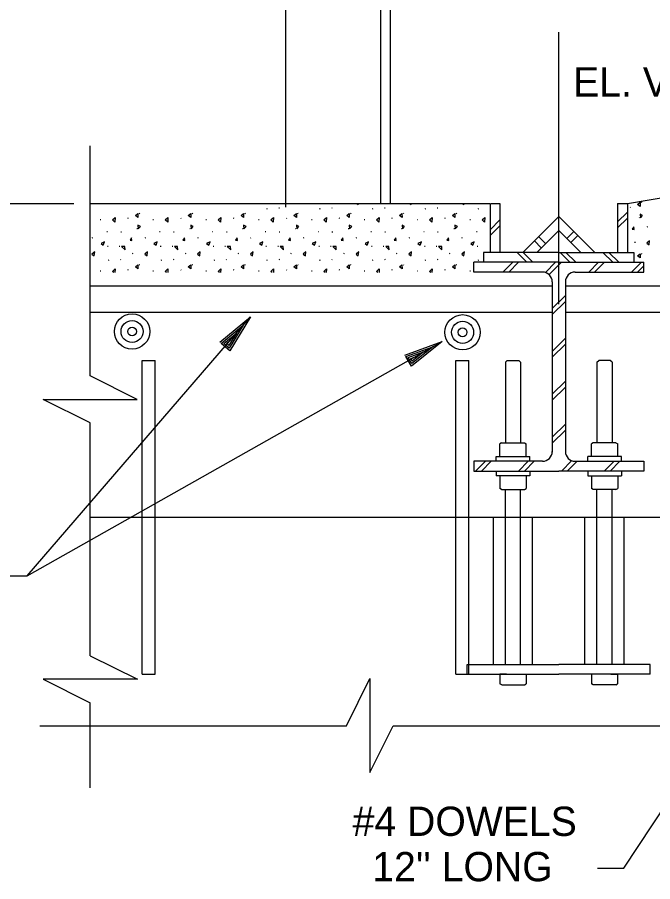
# Model space of a CAD drawing. Extents: x 0 to 320, y -4 to 473.
# Drawn here: x 7.218 to 10.256, y 2.461 to 6.592 of the extents above; entities that cross this region are included whole.
import ezdxf

# ---------------------------------------------------------------- set-up
doc = ezdxf.new("R2010")
doc.units = 0
for name, color, linetype in [('Level 2', 7, 'Continuous'), ('Level 22', 7, 'Continuous'), ('Level 3', 7, 'Continuous'), ('Level 44', 7, 'Continuous'), ('Level 50', 7, 'Continuous')]:
    doc.layers.add(name, color=color, linetype=linetype)

msp = doc.modelspace()

# ---------------------------------------------------------------- linework, layer by layer
at = {"layer": 'Level 2'}
for p, q in [((8.5026, 5.6844), (8.5026, 8.1261)), ((8.9557, 5.7009), (8.9557, 8.1261)), ((9.0026, 5.7025), (9.0026, 8.1261)), ((10.1354, 5.7025), (10.8854, 5.8276)), ((7.5674, 5.7025), (9.4791, 5.7025)), ((9.4791, 5.7025), (9.4791, 5.4682)), ((9.4836, 5.7025), (9.526, 5.7025)), ((9.526, 5.7025), (9.526, 5.4682)), ((10.0885, 5.7025), (10.0885, 5.4682)), ((10.0885, 5.7025), (10.1354, 5.7025)), ((10.1354, 5.7025), (10.1354, 5.4682)), ((10.0885, 5.6139), (10.1354, 5.6608)), ((9.4791, 5.577), (9.526, 5.6238)), ((9.8072, 5.64), (9.6354, 5.4682)), ((9.8072, 5.64), (9.9791, 5.4682)), ((10.0885, 5.5856), (10.1354, 5.6325)), ((9.4791, 5.5487), (9.526, 5.5956)), ((9.8072, 5.5738), (9.7017, 5.4682)), ((9.7439, 5.5104), (9.7108, 5.5436)), ((9.8072, 5.5738), (9.9128, 5.4682)), ((9.8461, 5.5348), (9.8793, 5.568)), ((9.8651, 5.5159), (9.8983, 5.549)), ((9.7237, 5.4902), (9.6905, 5.5233)), ((9.8072, 5.4682), (9.4479, 5.4682)), ((9.4479, 5.4682), (9.4479, 5.4213)), ((9.6551, 5.4213), (9.6082, 5.4682)), ((9.6833, 5.4213), (9.6365, 5.4682)), ((9.8072, 5.4682), (10.1666, 5.4682)), ((9.8601, 5.4213), (9.8132, 5.4682)), ((9.8884, 5.4213), (9.8415, 5.4682)), ((10.0652, 5.4213), (10.0183, 5.4682)), ((10.0935, 5.4213), (10.0466, 5.4682)), ((10.1666, 5.4682), (10.1666, 5.4213)), ((9.8072, 5.4213), (9.401, 5.4213)), ((9.401, 5.3744), (9.401, 5.4213)), ((9.54, 5.3744), (9.5869, 5.4213)), ((9.5683, 5.3744), (9.6151, 5.4213)), ((9.7429, 5.3723), (9.7919, 5.4213)), ((9.7609, 5.362), (9.8202, 5.4213)), ((9.8072, 5.4213), (10.2135, 5.4213)), ((9.9501, 5.3744), (9.997, 5.4213)), ((9.9784, 5.3744), (10.0253, 5.4213)), ((10.1552, 5.3744), (10.202, 5.4213)), ((10.2135, 5.3744), (10.2135, 5.4213)), ((9.7291, 5.3744), (9.401, 5.3744)), ((9.8854, 5.3744), (10.2135, 5.3744)), ((10.1834, 5.3744), (10.2135, 5.4045)), ((9.776, 5.3068), (7.5674, 5.3068)), ((9.776, 5.3275), (9.776, 4.5135)), ((9.8385, 5.3275), (9.8385, 4.5135)), ((11.4166, 5.3068), (9.8385, 5.3068)), ((9.776, 5.2003), (9.8385, 5.2628)), ((9.776, 5.172), (9.8385, 5.2345)), ((9.776, 5.1818), (7.5674, 5.1818)), ((11.4166, 5.1818), (9.8385, 5.1818)), ((9.776, 4.9953), (9.8385, 5.0578)), ((9.776, 4.967), (9.8385, 5.0295)), ((7.8151, 3.4525), (7.8151, 4.9525)), ((7.8776, 3.4525), (7.8776, 4.9525)), ((9.3151, 3.4525), (9.3151, 4.9525)), ((9.3776, 3.4525), (9.3776, 4.9525)), ((9.5519, 4.9434), (9.561, 4.9525)), ((9.5521, 4.9434), (9.5521, 4.5583)), ((9.561, 4.9525), (9.6156, 4.9525)), ((9.6247, 4.9434), (9.6156, 4.9525)), ((9.6249, 4.9434), (9.6249, 4.5583)), ((9.9896, 4.9434), (9.9896, 4.5583)), ((9.9898, 4.9434), (9.9989, 4.9525)), ((10.0535, 4.9525), (9.9989, 4.9525)), ((10.0626, 4.9434), (10.0535, 4.9525)), ((10.0624, 4.9434), (10.0624, 4.5583)), ((9.776, 4.7902), (9.8385, 4.8527)), ((9.776, 4.7619), (9.8385, 4.8244)), ((9.776, 4.5851), (9.8385, 4.6476)), ((9.776, 4.5568), (9.8385, 4.6193)), ((9.5341, 4.5583), (9.5257, 4.5534)), ((9.5257, 4.4938), (9.5257, 4.5534)), ((9.5341, 4.5583), (9.6429, 4.5583)), ((9.6429, 4.5583), (9.6513, 4.5534)), ((9.6513, 4.4938), (9.6513, 4.5534)), ((9.9716, 4.5583), (9.9632, 4.5534)), ((9.9632, 4.4938), (9.9632, 4.5534)), ((10.0804, 4.5583), (9.9716, 4.5583)), ((10.0804, 4.5583), (10.0888, 4.5534)), ((10.0888, 4.4938), (10.0888, 4.5534)), ((9.7291, 4.4703), (9.401, 4.4703)), ((9.401, 4.4703), (9.401, 4.4235)), ((9.4093, 4.4235), (9.4561, 4.4703)), ((9.4376, 4.4235), (9.4844, 4.4703)), ((9.5082, 4.4938), (9.6688, 4.4938)), ((9.5082, 4.4703), (9.5082, 4.4938)), ((9.5521, 4.4915), (9.5521, 4.4938)), ((9.6143, 4.4235), (9.6612, 4.4703)), ((9.6249, 4.4915), (9.6249, 4.4938)), ((9.6426, 4.4235), (9.6895, 4.4703)), ((9.6688, 4.4703), (9.6688, 4.4938)), ((9.8194, 4.4235), (9.8692, 4.4732)), ((9.8477, 4.4235), (9.8946, 4.4703)), ((9.8854, 4.4703), (10.2135, 4.4703)), ((10.1063, 4.4938), (9.9457, 4.4938)), ((9.9457, 4.4703), (9.9457, 4.4938)), ((9.9896, 4.4915), (9.9896, 4.4938)), ((10.0245, 4.4235), (10.0713, 4.4703)), ((10.0527, 4.4235), (10.0996, 4.4703)), ((10.0624, 4.4915), (10.0624, 4.4938)), ((10.1063, 4.4703), (10.1063, 4.4938)), ((10.2135, 4.4703), (10.2135, 4.4235)), ((9.401, 4.4235), (9.8072, 4.4235)), ((9.5082, 4.4235), (9.5082, 4.4)), ((9.6688, 4.4235), (9.6688, 4.4)), ((10.2135, 4.4235), (9.8072, 4.4235)), ((9.9457, 4.4235), (9.9457, 4.4)), ((10.1063, 4.4235), (10.1063, 4.4)), ((9.6688, 4.4), (9.5082, 4.4)), ((9.5257, 4.4), (9.5257, 4.3404)), ((9.5521, 4.4023), (9.5521, 4.4)), ((9.6249, 4.4023), (9.6249, 4.4)), ((9.6513, 4.4), (9.6513, 4.3404)), ((9.9457, 4.4), (10.1063, 4.4)), ((9.9632, 4.4), (9.9632, 4.3404)), ((9.9896, 4.4023), (9.9896, 4.4)), ((10.0624, 4.4023), (10.0624, 4.4)), ((10.0888, 4.4), (10.0888, 4.3404)), ((9.5341, 4.3355), (9.5257, 4.3404)), ((9.6429, 4.3355), (9.6513, 4.3404)), ((9.9716, 4.3355), (9.9632, 4.3404)), ((10.0804, 4.3355), (10.0888, 4.3404)), ((9.5341, 4.3355), (9.6429, 4.3355)), ((9.5521, 3.4994), (9.5521, 4.3355)), ((9.6249, 3.4994), (9.6249, 4.3355)), ((10.0804, 4.3355), (9.9716, 4.3355)), ((9.9896, 3.4994), (9.9896, 4.3355)), ((10.0624, 3.4994), (10.0624, 4.3355)), ((7.5674, 4.2025), (14.9124, 4.2025)), ((9.4947, 3.4994), (9.4947, 4.2025)), ((9.6822, 3.4994), (9.6822, 4.2025)), ((9.9322, 3.4994), (9.9322, 4.2025)), ((10.1197, 3.4994), (10.1197, 4.2025)), ((9.3697, 3.4994), (9.8072, 3.4994)), ((9.3697, 3.4525), (9.3697, 3.4994)), ((10.2447, 3.4994), (9.8072, 3.4994)), ((10.2447, 3.4525), (10.2447, 3.4994)), ((9.3697, 3.4525), (9.8072, 3.4525)), ((9.5578, 3.4523), (9.526, 3.4523)), ((9.526, 3.4523), (9.526, 3.4063)), ((9.5525, 3.4546), (9.5525, 3.4523)), ((9.6252, 3.4546), (9.6252, 3.4523)), ((9.6517, 3.4523), (9.6517, 3.4063)), ((10.2447, 3.4525), (9.8072, 3.4525)), ((9.9628, 3.4523), (9.9628, 3.4063)), ((9.9893, 3.4546), (9.9893, 3.4523)), ((10.0567, 3.4523), (10.0884, 3.4523)), ((10.062, 3.4546), (10.062, 3.4523)), ((10.0884, 3.4523), (10.0884, 3.4063)), ((9.5345, 3.4014), (9.526, 3.4063)), ((9.5345, 3.4014), (9.6432, 3.4014)), ((9.6432, 3.4014), (9.6517, 3.4063)), ((9.9713, 3.4014), (9.9628, 3.4063)), ((10.08, 3.4014), (9.9713, 3.4014)), ((10.08, 3.4014), (10.0884, 3.4063))]:
    msp.add_line(p, q, dxfattribs=at)
for centre, start, end in [((9.7291, 5.3275), 0, 90), ((9.8854, 5.3275), 90, 180), ((9.7291, 4.5172), 270, 360), ((9.8854, 4.5172), 180, 270)]:
    msp.add_arc(centre, 0.0469, start, end, dxfattribs=at)
at = {"layer": 'Level 3'}
for p, q in [((8.3326, 5.1604), (8.3326, 5.1604)), ((8.2986, 5.1211), (8.2986, 5.1211))]:
    msp.add_line(p, q, dxfattribs=at)
for points in [[(6.9886, 3.9226), (7.2659, 3.9226), (8.3326, 5.1604)], [(8.187, 5.039), (8.3326, 5.1604), (8.234, 4.9985), (8.1938, 5.0331), (8.2986, 5.1211), (8.2316, 5.0111), (8.2059, 5.0333), (8.266, 5.0832), (8.2293, 5.0237), (8.2187, 5.0329), (8.232, 5.0438)], [(9.9929, 2.5257), (10.1174, 2.5257), (10.8098, 3.5702)]]:
    msp.add_lwpolyline(points, dxfattribs=at)
at = {"layer": 'Level 44'}
for p, q in [((7.5674, 4.8785), (7.5674, 5.9777)), ((6.4616, 5.7025), (7.4884, 5.7025)), ((10.205, 5.7061), (10.2022, 5.7078)), ((8.4132, 5.6765), (8.4098, 5.6756)), ((8.4714, 5.6799), (8.469, 5.679)), ((8.6657, 5.6765), (8.6623, 5.6756)), ((8.7239, 5.6799), (8.7215, 5.679)), ((8.9182, 5.6765), (8.9148, 5.6756)), ((8.9764, 5.6799), (8.974, 5.679)), ((9.1707, 5.6765), (9.1673, 5.6756)), ((9.2289, 5.6799), (9.2265, 5.679)), ((9.4232, 5.6765), (9.4198, 5.6756)), ((10.1505, 5.6829), (10.1478, 5.6841)), ((7.6174, 5.6242), (7.6147, 5.6239)), ((7.75, 5.6302), (7.7473, 5.6314)), ((7.8044, 5.6534), (7.8016, 5.6551)), ((7.8699, 5.6242), (7.8672, 5.6239)), ((8.0025, 5.6302), (7.9998, 5.6314)), ((8.0569, 5.6534), (8.0541, 5.6551)), ((8.1224, 5.6242), (8.1197, 5.6239)), ((8.255, 5.6302), (8.2523, 5.6314)), ((8.3094, 5.6534), (8.3066, 5.6551)), ((8.3749, 5.6242), (8.3722, 5.6239)), ((8.5075, 5.6302), (8.5048, 5.6314)), ((8.5619, 5.6534), (8.5591, 5.6551)), ((8.6274, 5.6242), (8.6247, 5.6239)), ((8.76, 5.6302), (8.7573, 5.6314)), ((8.8144, 5.6534), (8.8116, 5.6551)), ((8.8799, 5.6242), (8.8772, 5.6239)), ((9.0125, 5.6302), (9.0098, 5.6314)), ((9.0669, 5.6534), (9.0641, 5.6551)), ((9.1324, 5.6242), (9.1297, 5.6239)), ((9.265, 5.6302), (9.2623, 5.6314)), ((9.3194, 5.6534), (9.3166, 5.6551)), ((9.3849, 5.6242), (9.3822, 5.6239)), ((10.1937, 5.6343), (10.1912, 5.6345)), ((7.7932, 5.5816), (7.7907, 5.5818)), ((8.0457, 5.5816), (8.0432, 5.5818)), ((8.2982, 5.5816), (8.2957, 5.5818)), ((8.5507, 5.5816), (8.5482, 5.5818)), ((8.8032, 5.5816), (8.8007, 5.5818)), ((9.0557, 5.5816), (9.0532, 5.5818)), ((9.3082, 5.5816), (9.3057, 5.5818)), ((10.2313, 5.5903), (10.2283, 5.5888)), ((7.5782, 5.5375), (7.5752, 5.536)), ((7.649, 5.567), (7.6465, 5.5674)), ((7.7162, 5.5649), (7.7129, 5.5649)), ((7.8307, 5.5375), (7.8277, 5.536)), ((7.9015, 5.567), (7.899, 5.5674)), ((7.9687, 5.5649), (7.9654, 5.5649)), ((8.0832, 5.5375), (8.0802, 5.536)), ((8.154, 5.567), (8.1515, 5.5674)), ((8.2212, 5.5649), (8.2179, 5.5649)), ((8.3357, 5.5375), (8.3327, 5.536)), ((8.4065, 5.567), (8.404, 5.5674)), ((8.4737, 5.5649), (8.4704, 5.5649)), ((8.5882, 5.5375), (8.5852, 5.536)), ((8.659, 5.567), (8.6565, 5.5674)), ((8.7262, 5.5649), (8.7229, 5.5649)), ((8.8407, 5.5375), (8.8377, 5.536)), ((8.9115, 5.567), (8.909, 5.5674)), ((8.9787, 5.5649), (8.9754, 5.5649)), ((9.0932, 5.5375), (9.0902, 5.536)), ((9.164, 5.567), (9.1615, 5.5674)), ((9.2312, 5.5649), (9.2279, 5.5649)), ((9.3457, 5.5375), (9.3427, 5.536)), ((9.4165, 5.567), (9.414, 5.5674)), ((7.653, 5.496), (7.6496, 5.496)), ((7.709, 5.4972), (7.7058, 5.4972)), ((7.9055, 5.496), (7.9021, 5.496)), ((7.9615, 5.4972), (7.9583, 5.4972)), ((8.158, 5.496), (8.1546, 5.496)), ((8.214, 5.4972), (8.2108, 5.4972)), ((8.4105, 5.496), (8.4071, 5.496)), ((8.4665, 5.4972), (8.4633, 5.4972)), ((8.663, 5.496), (8.6596, 5.496)), ((8.719, 5.4972), (8.7158, 5.4972)), ((8.9155, 5.496), (8.9121, 5.496)), ((8.9715, 5.4972), (8.9683, 5.4972)), ((9.168, 5.496), (9.1646, 5.496)), ((9.224, 5.4972), (9.2208, 5.4972)), ((9.4205, 5.496), (9.4171, 5.496)), ((10.1732, 5.515), (10.1699, 5.5156)), ((7.7726, 5.4623), (7.7694, 5.4629)), ((8.0251, 5.4623), (8.0219, 5.4629)), ((8.2776, 5.4623), (8.2744, 5.4629)), ((8.5301, 5.4623), (8.5269, 5.4629)), ((8.7826, 5.4623), (8.7794, 5.4629)), ((9.0351, 5.4623), (9.0319, 5.4629)), ((9.2876, 5.4623), (9.2844, 5.4629)), ((10.205, 5.4602), (10.2022, 5.4619)), ((7.6557, 5.4306), (7.6523, 5.4297)), ((7.7139, 5.434), (7.7115, 5.433)), ((7.9082, 5.4306), (7.9048, 5.4297)), ((7.9664, 5.434), (7.964, 5.433)), ((8.1607, 5.4306), (8.1573, 5.4297)), ((8.2189, 5.434), (8.2165, 5.433)), ((8.4132, 5.4306), (8.4098, 5.4297)), ((8.4714, 5.434), (8.469, 5.433)), ((8.6657, 5.4306), (8.6623, 5.4297)), ((8.7239, 5.434), (8.7215, 5.433)), ((8.9182, 5.4306), (8.9148, 5.4297)), ((8.9764, 5.434), (8.974, 5.433)), ((9.1707, 5.4306), (9.1673, 5.4297)), ((9.2289, 5.434), (9.2265, 5.433)), ((9.4232, 5.4306), (9.4198, 5.4297)), ((7.6174, 5.3782), (7.6147, 5.378)), ((7.75, 5.3842), (7.7473, 5.3855)), ((7.8044, 5.4075), (7.8016, 5.4092)), ((7.8699, 5.3782), (7.8672, 5.378)), ((8.0025, 5.3842), (7.9998, 5.3855)), ((8.0569, 5.4075), (8.0541, 5.4092)), ((8.1224, 5.3782), (8.1197, 5.378)), ((8.255, 5.3842), (8.2523, 5.3855)), ((8.3094, 5.4075), (8.3066, 5.4092)), ((8.3749, 5.3782), (8.3722, 5.378)), ((8.5075, 5.3842), (8.5048, 5.3855)), ((8.5619, 5.4075), (8.5591, 5.4092)), ((8.6274, 5.3782), (8.6247, 5.378)), ((8.76, 5.3842), (8.7573, 5.3855)), ((8.8144, 5.4075), (8.8116, 5.4092)), ((8.8799, 5.3782), (8.8772, 5.378)), ((9.0125, 5.3842), (9.0098, 5.3855)), ((9.0669, 5.4075), (9.0641, 5.4092)), ((9.1324, 5.3782), (9.1297, 5.378)), ((9.265, 5.3842), (9.2623, 5.3855)), ((9.3194, 5.4075), (9.3166, 5.4092)), ((9.3849, 5.3782), (9.3822, 5.378)), ((7.8151, 4.9525), (7.8776, 4.9525)), ((9.3151, 4.9525), (9.3776, 4.9525)), ((7.5674, 3.5408), (7.5674, 4.6542)), ((7.8151, 3.4525), (7.8776, 3.4525)), ((9.3151, 3.4525), (9.3776, 3.4525)), ((7.5674, 2.9099), (7.5674, 3.3166)), ((7.3263, 3.2068), (8.7916, 3.2068)), ((9.0159, 3.2068), (10.7577, 3.2068))]:
    msp.add_line(p, q, dxfattribs=at)
for points in [[(8.8422, 5.7025), (8.8487, 5.6971), (8.8493, 5.7025)], [(9.0947, 5.7025), (9.1012, 5.6971), (9.1018, 5.7025)], [(9.3472, 5.7025), (9.3537, 5.6971), (9.3543, 5.7025)], [(7.68, 5.3718), (7.6734, 5.3779), (7.6862, 5.3894), (7.6852, 5.3718)], [(7.9325, 5.3718), (7.9259, 5.3779), (7.9387, 5.3894), (7.9377, 5.3718)], [(8.185, 5.3718), (8.1784, 5.3779), (8.1912, 5.3894), (8.1902, 5.3718)], [(8.4375, 5.3718), (8.4309, 5.3779), (8.4437, 5.3894), (8.4427, 5.3718)], [(8.69, 5.3718), (8.6834, 5.3779), (8.6962, 5.3894), (8.6952, 5.3718)], [(8.9425, 5.3718), (8.9359, 5.3779), (8.9487, 5.3894), (8.9477, 5.3718)], [(9.195, 5.3718), (9.1884, 5.3779), (9.2012, 5.3894), (9.2002, 5.3718)]]:
    msp.add_lwpolyline(points, dxfattribs=at)
for points in [[(10.1961, 5.6884), (10.1841, 5.6975), (10.1956, 5.7077)], [(7.685, 5.6132), (7.6734, 5.6239), (7.6862, 5.6353)], [(7.7955, 5.6357), (7.7835, 5.6448), (7.795, 5.655)], [(7.9375, 5.6132), (7.9259, 5.6239), (7.9387, 5.6353)], [(8.048, 5.6357), (8.036, 5.6448), (8.0475, 5.655)], [(8.19, 5.6132), (8.1784, 5.6239), (8.1912, 5.6353)], [(8.3005, 5.6357), (8.2885, 5.6448), (8.3, 5.655)], [(8.4425, 5.6132), (8.4309, 5.6239), (8.4437, 5.6353)], [(8.553, 5.6357), (8.541, 5.6448), (8.5525, 5.655)], [(8.695, 5.6132), (8.6834, 5.6239), (8.6962, 5.6353)], [(8.8055, 5.6357), (8.7935, 5.6448), (8.805, 5.655)], [(8.9475, 5.6132), (8.9359, 5.6239), (8.9487, 5.6353)], [(9.058, 5.6357), (9.046, 5.6448), (9.0575, 5.655)], [(9.2, 5.6132), (9.1884, 5.6239), (9.2012, 5.6353)], [(9.3105, 5.6357), (9.2985, 5.6448), (9.31, 5.655)], [(9.4525, 5.6132), (9.4409, 5.6239), (9.4537, 5.6353)], [(10.1973, 5.6334), (10.208, 5.6454), (10.1961, 5.6518)], [(7.7968, 5.5807), (7.8075, 5.5927), (7.7955, 5.5991)], [(8.0493, 5.5807), (8.06, 5.5927), (8.048, 5.5991)], [(8.3018, 5.5807), (8.3125, 5.5927), (8.3005, 5.5991)], [(8.5543, 5.5807), (8.565, 5.5927), (8.553, 5.5991)], [(8.8068, 5.5807), (8.8175, 5.5927), (8.8055, 5.5991)], [(9.0593, 5.5807), (9.07, 5.5927), (9.058, 5.5991)], [(9.3118, 5.5807), (9.3225, 5.5927), (9.3105, 5.5991)], [(10.1673, 5.5776), (10.1655, 5.5913), (10.1578, 5.5798)], [(7.7667, 5.5249), (7.765, 5.5385), (7.7573, 5.5271)], [(8.0192, 5.5249), (8.0175, 5.5385), (8.0098, 5.5271)], [(8.2717, 5.5249), (8.27, 5.5385), (8.2623, 5.5271)], [(8.5242, 5.5249), (8.5225, 5.5385), (8.5148, 5.5271)], [(8.7767, 5.5249), (8.775, 5.5385), (8.7673, 5.5271)], [(9.0292, 5.5249), (9.0275, 5.5385), (9.0198, 5.5271)], [(9.2817, 5.5249), (9.28, 5.5385), (9.2723, 5.5271)], [(7.6294, 5.5034), (7.6353, 5.5187), (7.6187, 5.5106)], [(7.7324, 5.4964), (7.7174, 5.4972), (7.7337, 5.4806)], [(7.8819, 5.5034), (7.8878, 5.5187), (7.8712, 5.5106)], [(7.9849, 5.4964), (7.9699, 5.4972), (7.9862, 5.4806)], [(8.1344, 5.5034), (8.1403, 5.5187), (8.1237, 5.5106)], [(8.2374, 5.4964), (8.2224, 5.4972), (8.2387, 5.4806)], [(8.3869, 5.5034), (8.3928, 5.5187), (8.3762, 5.5106)], [(8.4899, 5.4964), (8.4749, 5.4972), (8.4912, 5.4806)], [(8.6394, 5.5034), (8.6453, 5.5187), (8.6287, 5.5106)], [(8.7424, 5.4964), (8.7274, 5.4972), (8.7437, 5.4806)], [(8.8919, 5.5034), (8.8978, 5.5187), (8.8812, 5.5106)], [(8.9949, 5.4964), (8.9799, 5.4972), (8.9962, 5.4806)], [(9.1444, 5.5034), (9.1503, 5.5187), (9.1337, 5.5106)], [(9.2474, 5.4964), (9.2324, 5.4972), (9.2487, 5.4806)], [(9.3969, 5.5034), (9.4028, 5.5187), (9.3862, 5.5106)], [(10.2414, 5.524), (10.2286, 5.5128), (10.2392, 5.5039)], [(7.5884, 5.4713), (7.5755, 5.4601), (7.5862, 5.4512)], [(7.8409, 5.4713), (7.828, 5.4601), (7.8387, 5.4512)], [(8.0934, 5.4713), (8.0805, 5.4601), (8.0912, 5.4512)], [(8.3459, 5.4713), (8.333, 5.4601), (8.3437, 5.4512)], [(8.5984, 5.4713), (8.5855, 5.4601), (8.5962, 5.4512)], [(8.8509, 5.4713), (8.838, 5.4601), (8.8487, 5.4512)], [(9.1034, 5.4713), (9.0905, 5.4601), (9.1012, 5.4512)], [(9.3559, 5.4713), (9.343, 5.4601), (9.3537, 5.4512)], [(10.1961, 5.4425), (10.1841, 5.4516), (10.1956, 5.4618)], [(7.7955, 5.3898), (7.7835, 5.3989), (7.795, 5.409)], [(8.048, 5.3898), (8.036, 5.3989), (8.0475, 5.409)], [(8.3005, 5.3898), (8.2885, 5.3989), (8.3, 5.409)], [(8.553, 5.3898), (8.541, 5.3989), (8.5525, 5.409)], [(8.8055, 5.3898), (8.7935, 5.3989), (8.805, 5.409)], [(9.058, 5.3898), (9.046, 5.3989), (9.0575, 5.409)], [(9.3105, 5.3898), (9.2985, 5.3989), (9.31, 5.409)]]:
    msp.add_lwpolyline(points, close=True, dxfattribs=at)
at = {"layer": 'Level 50'}
for p, q in [((9.8072, 5.2206), (9.8072, 6.5203)), ((7.2659, 3.9226), (9.2499, 5.0431)), ((9.2499, 5.0431), (9.2499, 5.0431)), ((9.2046, 5.0175), (9.2046, 5.0175)), ((7.7919, 4.766), (7.5674, 4.8785)), ((7.5674, 4.6542), (7.3424, 4.766)), ((7.3424, 4.766), (7.7919, 4.766)), ((7.5674, 3.5408), (7.7924, 3.4291)), ((7.7924, 3.4291), (7.3429, 3.4291)), ((7.3429, 3.4291), (7.5674, 3.3166)), ((8.7916, 3.2068), (8.9034, 3.4318)), ((8.9034, 3.4318), (8.9034, 2.9823)), ((8.9034, 2.9823), (9.0159, 3.2068))]:
    msp.add_line(p, q, dxfattribs=at)
msp.add_lwpolyline([(9.0718, 4.9781), (9.2499, 5.0431), (9.1023, 4.9241), (9.0762, 4.9703), (9.2046, 5.0175), (9.1043, 4.9368), (9.0876, 4.9664), (9.161, 4.9929), (9.1064, 4.9494), (9.0995, 4.9616), (9.1158, 4.9673)], dxfattribs=at)
for centre, radius in [((7.7674, 5.0904), 0.0844), ((9.3472, 5.0865), 0.0844), ((7.7674, 5.0904), 0.0527), ((9.3472, 5.0865), 0.0527), ((7.7674, 5.0904), 0.0211), ((9.3472, 5.0865), 0.0211)]:
    msp.add_circle(centre, radius, dxfattribs=at)

# ---------------------------------------------------------------- texts
at = {"layer": 'Level 22'}
for s, p in [('#4 DOWELS', (8.8215, 2.68)), ("12'' LONG", (8.9156, 2.4632))]:
    msp.add_text(s, height=0.14002, dxfattribs=at).set_placement(p)
at = {"layer": 'Level 50'}
msp.add_text('EL. VARIES', height=0.14002, dxfattribs=at).set_placement((9.8759, 6.2133))

doc.saveas('drawing.dxf')
